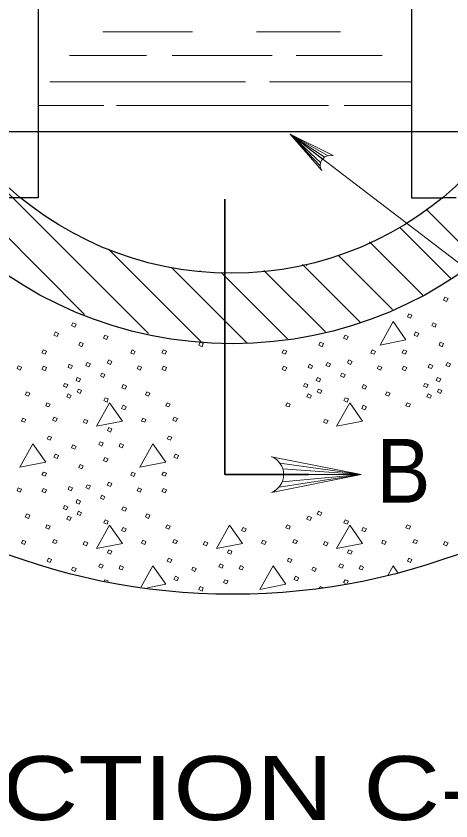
# Model space of a CAD drawing. Extents: x 1083.1 to 1117.1, y 719.4 to 741.4.
# Drawn here: x 1090.16 to 1091.793, y 732.034 to 735.057 of the extents above; entities that cross this region are included whole.
import ezdxf
from ezdxf.enums import TextEntityAlignment as Align

# ---------------------------------------------------------------- set-up
doc = ezdxf.new("R2010")
doc.units = 0
doc.header["$LTSCALE"] = 0.062
doc.linetypes.add('LONG_DASHED', pattern=[7.5, 6, -1.5])
doc.layers.add('1', color=7, linetype='Continuous', lineweight=13)

msp = doc.modelspace()

# ---------------------------------------------------------------- linework, layer by layer
at = {"layer": '1', "lineweight": 25}
for p, q in [((1090.24283, 736.2775), (1090.24283, 734.37467)), ((1091.64517, 736.2775), (1091.64517, 734.37467)), ((1090.24283, 734.62317), (1091.64517, 734.62317)), ((1091.64517, 734.37467), (1091.76217, 734.37467))]:
    msp.add_line(p, q, dxfattribs=at)
at = {"layer": '1'}
for p, q in [((1090.65658, 733.86433), (1089.491, 735.02975)), ((1090.48583, 734.99833), (1090.82275, 734.99833)), ((1091.06233, 734.99833), (1091.37825, 734.99833)), ((1090.36083, 734.90842), (1090.64908, 734.90842)), ((1090.74625, 734.90842), (1091.12133, 734.90842)), ((1091.21167, 734.90842), (1091.53458, 734.90842)), ((1090.41642, 733.93658), (1089.56367, 734.78925)), ((1090.28625, 734.81042), (1091.02067, 734.81042)), ((1091.11092, 734.81042), (1091.64517, 734.81042)), ((1090.24283, 734.72175), (1090.48883, 734.72175)), ((1090.53692, 734.72175), (1091.33317, 734.72175)), ((1091.39225, 734.72175), (1091.64517, 734.72175)), ((1091.31033, 734.5195), (1091.18858, 734.61392)), ((1091.30367, 734.50625), (1091.18858, 734.61392)), ((1091.30217, 734.49425), (1091.18858, 734.61392)), ((1091.31858, 734.52742), (1091.18858, 734.61392)), ((1091.32975, 734.53292), (1091.18858, 734.61392)), ((1091.89175, 734.13983), (1091.69958, 734.33208)), ((1091.79133, 734.07233), (1091.6, 734.26367)), ((1091.6875, 734.00842), (1091.487, 734.20883)), ((1090.854, 733.83467), (1090.50642, 734.18217)), ((1091.57283, 733.95525), (1091.36933, 734.15867)), ((1091.45242, 733.90775), (1091.236, 734.12417)), ((1091.02908, 733.8275), (1090.74475, 734.11175)), ((1091.17933, 733.84508), (1090.93025, 734.09417)), ((1091.32158, 733.87075), (1091.0905, 734.10183)), ((1091.15075, 733.3775), (1091.45517, 733.33492)), ((1091.16108, 733.35642), (1091.45517, 733.33492)), ((1091.14717, 733.28783), (1091.45517, 733.33492)), ((1091.15883, 733.30758), (1091.45517, 733.33492)), ((1091.16417, 733.33492), (1091.45517, 733.33492)), ((1090.67358, 732.99158), (1090.62983, 732.91325)), ((1091.57567, 732.99158), (1091.55717, 732.9585)), ((1091.59358, 732.96592), (1091.57567, 732.99158)), ((1090.49108, 732.93608), (1090.49317, 732.94017)), ((1091.29925, 732.908), (1091.30183, 732.91408))]:
    msp.add_line(p, q, dxfattribs=at)
at = {"layer": '1', "linetype": 'LONG_DASHED', "lineweight": 25}
for p, q in [((1087.08633, 734.62317), (1090.24283, 734.62317)), ((1091.64517, 734.62317), (1095.91342, 734.62317)), ((1090.24283, 734.37467), (1088.72042, 734.36742)), ((1093.22825, 734.37467), (1091.76217, 734.37467))]:
    msp.add_line(p, q, dxfattribs=at)
at = {"layer": '1', "lineweight": 35}
for p, q in [((1090.944, 734.37), (1090.944, 733.33492)), ((1090.944, 733.33492), (1091.25742, 733.33492))]:
    msp.add_line(p, q, dxfattribs=at)
at = {"layer": '1'}
for points in [[(1091.30742, 734.47658), (1091.18858, 734.61392), (1091.35108, 734.53292)], [(1091.18858, 734.61392), (1092.91808, 733.29283), (1093.25458, 733.29283)], [(1091.25342, 734.12575), (1091.25125, 734.12067), (1091.245, 734.12317)], [(1090.85208, 734.09967), (1090.85158, 734.0985), (1090.84875, 734.09983)], [(1091.11892, 733.26767), (1091.45517, 733.33492), (1091.11892, 733.40217)], [(1090.65342, 732.90942), (1090.72183, 732.92275), (1090.67358, 732.99158)], [(1090.49317, 732.94017), (1090.505, 732.93542), (1090.50433, 732.93392)], [(1091.30183, 732.91408), (1091.31375, 732.90933), (1091.31367, 732.90917)], [(1091.39742, 732.926), (1091.38967, 732.92908), (1091.39525, 732.94017)], [(1091.39525, 732.94017), (1091.40708, 732.93542), (1091.403, 732.92708)]]:
    msp.add_lwpolyline(points, dxfattribs=at)
for points in [[(1091.77033, 734.00117), (1091.78217, 733.99642), (1091.77667, 733.98533), (1091.76475, 733.99008)], [(1091.63417, 733.93867), (1091.64608, 733.93392), (1091.64133, 733.92283), (1091.62942, 733.92758)], [(1090.37292, 733.90542), (1090.38475, 733.89992), (1090.38, 733.88883), (1090.36808, 733.89433)], [(1091.57567, 733.90942), (1091.52658, 733.82158), (1091.62392, 733.84058)], [(1091.726, 733.90542), (1091.73783, 733.89992), (1091.73308, 733.88883), (1091.72125, 733.89433)], [(1090.30717, 733.87067), (1090.31908, 733.86508), (1090.3135, 733.854), (1090.30167, 733.85875)], [(1090.49317, 733.858), (1090.505, 733.85325), (1090.4995, 733.84217), (1090.48758, 733.84692)], [(1091.39525, 733.858), (1091.40708, 733.85325), (1091.40158, 733.84217), (1091.38967, 733.84692)], [(1091.66033, 733.87067), (1091.67217, 733.86508), (1091.66667, 733.854), (1091.65475, 733.85875)], [(1090.39975, 733.83183), (1090.41167, 733.82708), (1090.40692, 733.81525), (1090.395, 733.82075)], [(1090.85083, 733.83183), (1090.86267, 733.82708), (1090.85792, 733.81525), (1090.84608, 733.82075)], [(1091.30183, 733.83183), (1091.31375, 733.82708), (1091.309, 733.81525), (1091.29708, 733.82075)], [(1091.75292, 733.83183), (1091.76475, 733.82708), (1091.76, 733.81525), (1091.74817, 733.82075)], [(1090.26208, 733.80342), (1090.274, 733.79858), (1090.26842, 733.78758), (1090.25658, 733.79233)], [(1090.59525, 733.80342), (1090.60708, 733.79783), (1090.60233, 733.78675), (1090.5905, 733.7915)], [(1090.71317, 733.80342), (1090.725, 733.79858), (1090.7195, 733.78758), (1090.70758, 733.79233)], [(1091.16417, 733.80342), (1091.176, 733.79858), (1091.1705, 733.78758), (1091.15867, 733.79233)], [(1091.49733, 733.80342), (1091.50917, 733.79783), (1091.50442, 733.78675), (1091.49258, 733.7915)], [(1091.61517, 733.80342), (1091.62708, 733.79858), (1091.6215, 733.78758), (1091.60967, 733.79233)], [(1090.50742, 733.76542), (1090.51925, 733.75983), (1090.51375, 733.74875), (1090.50183, 733.75433)], [(1091.4095, 733.76542), (1091.42133, 733.75983), (1091.41583, 733.74875), (1091.40392, 733.75433)], [(1090.16792, 733.744), (1090.17983, 733.7385), (1090.17508, 733.72742), (1090.16317, 733.73292)], [(1090.26208, 733.74167), (1090.274, 733.73692), (1090.26842, 733.72508), (1090.25658, 733.73058)], [(1090.35942, 733.74958), (1090.37125, 733.744), (1090.36658, 733.73292), (1090.35467, 733.73767)], [(1090.42667, 733.75592), (1090.43858, 733.75117), (1090.433, 733.73925), (1090.42117, 733.74483)], [(1090.619, 733.744), (1090.63083, 733.7385), (1090.62608, 733.72742), (1090.61425, 733.73292)], [(1090.71317, 733.74167), (1090.725, 733.73692), (1090.7195, 733.72508), (1090.70758, 733.73058)], [(1091.16417, 733.74167), (1091.176, 733.73692), (1091.1705, 733.72508), (1091.15867, 733.73058)], [(1091.2615, 733.74958), (1091.27333, 733.744), (1091.26858, 733.73292), (1091.25675, 733.73767)], [(1091.32875, 733.75592), (1091.34067, 733.75117), (1091.33508, 733.73925), (1091.32325, 733.74483)], [(1091.521, 733.744), (1091.53292, 733.7385), (1091.52817, 733.72742), (1091.51633, 733.73292)], [(1091.61517, 733.74167), (1091.62708, 733.73692), (1091.6215, 733.72508), (1091.60967, 733.73058)], [(1091.7125, 733.74958), (1091.72442, 733.744), (1091.71967, 733.73292), (1091.70775, 733.73767)], [(1091.77983, 733.75592), (1091.79167, 733.75117), (1091.78608, 733.73925), (1091.77425, 733.74483)], [(1090.3895, 733.69975), (1090.40133, 733.69417), (1090.39658, 733.68308), (1090.38475, 733.68783)], [(1090.48125, 733.71633), (1090.49317, 733.71083), (1090.48842, 733.69975), (1090.4765, 733.70525)], [(1091.29158, 733.69975), (1091.30342, 733.69417), (1091.29867, 733.68308), (1091.28683, 733.68783)], [(1091.38333, 733.71633), (1091.39525, 733.71083), (1091.3905, 733.69975), (1091.37858, 733.70525)], [(1091.74258, 733.69975), (1091.7545, 733.69417), (1091.74975, 733.68308), (1091.73783, 733.68783)], [(1090.342, 733.67758), (1090.35392, 733.67283), (1090.34917, 733.66175), (1090.33725, 733.6665)], [(1090.562, 733.67283), (1090.57383, 733.66725), (1090.56908, 733.65625), (1090.55725, 733.66092)], [(1091.24408, 733.67758), (1091.25592, 733.67283), (1091.25125, 733.66175), (1091.23933, 733.6665)], [(1091.46408, 733.67283), (1091.47592, 733.66725), (1091.47117, 733.65625), (1091.45933, 733.66092)], [(1091.69517, 733.67758), (1091.707, 733.67283), (1091.70225, 733.66175), (1091.69042, 733.6665)], [(1090.19958, 733.64592), (1090.21142, 733.64117), (1090.20592, 733.62933), (1090.194, 733.63483)], [(1090.39342, 733.65625), (1090.40533, 733.65067), (1090.40058, 733.63958), (1090.38867, 733.64517)], [(1090.65058, 733.64592), (1090.6625, 733.64117), (1090.65692, 733.62933), (1090.64508, 733.63483)], [(1091.2955, 733.65625), (1091.30742, 733.65067), (1091.30267, 733.63958), (1091.29075, 733.64517)], [(1091.55267, 733.64592), (1091.56458, 733.64117), (1091.559, 733.62933), (1091.54717, 733.63483)], [(1091.74658, 733.65625), (1091.75842, 733.65067), (1091.75367, 733.63958), (1091.74183, 733.64517)], [(1090.35467, 733.638), (1090.36658, 733.6325), (1090.36183, 733.62142), (1090.34992, 733.62692)], [(1090.49392, 733.62375), (1090.50583, 733.619), (1090.50108, 733.60717), (1090.48917, 733.61267)], [(1091.25675, 733.638), (1091.26858, 733.6325), (1091.26383, 733.62142), (1091.252, 733.62692)], [(1091.396, 733.62375), (1091.40792, 733.619), (1091.40317, 733.60717), (1091.39125, 733.61267)], [(1091.70775, 733.638), (1091.71967, 733.6325), (1091.71492, 733.62142), (1091.703, 733.62692)], [(1090.27558, 733.60475), (1090.28742, 733.6), (1090.28267, 733.58892), (1090.27083, 733.59367)], [(1090.51058, 733.604), (1090.4615, 733.51617), (1090.55883, 733.53517)], [(1090.56117, 733.59525), (1090.57308, 733.58975), (1090.5675, 733.57867), (1090.55567, 733.58342)], [(1090.72658, 733.60475), (1090.73842, 733.6), (1090.73367, 733.58892), (1090.72183, 733.59367)], [(1091.17758, 733.60475), (1091.1895, 733.6), (1091.18475, 733.58892), (1091.17283, 733.59367)], [(1091.41267, 733.604), (1091.36358, 733.51617), (1091.46092, 733.53517)], [(1091.46325, 733.59525), (1091.47517, 733.58975), (1091.46958, 733.57867), (1091.45775, 733.58342)], [(1091.62867, 733.60475), (1091.6405, 733.6), (1091.63575, 733.58892), (1091.62392, 733.59367)], [(1090.30242, 733.55017), (1090.31433, 733.54542), (1090.30875, 733.53433), (1090.29692, 733.53908)], [(1090.7535, 733.55017), (1090.76533, 733.54542), (1090.75983, 733.53433), (1090.74792, 733.53908)], [(1090.18458, 733.547), (1090.19642, 733.54225), (1090.19167, 733.53117), (1090.17983, 733.53592)], [(1090.41717, 733.54225), (1090.42908, 733.5375), (1090.4235, 733.52642), (1090.41167, 733.53117)], [(1090.63558, 733.547), (1090.64742, 733.54225), (1090.64267, 733.53117), (1090.63083, 733.53592)], [(1091.31925, 733.54225), (1091.33117, 733.5375), (1091.32558, 733.52642), (1091.31375, 733.53117)], [(1090.50742, 733.51142), (1090.51925, 733.50667), (1090.5145, 733.49483), (1090.50267, 733.50033)], [(1090.28108, 733.47975), (1090.29292, 733.475), (1090.28817, 733.46392), (1090.27633, 733.46867)], [(1090.47492, 733.45842), (1090.48683, 733.45367), (1090.48208, 733.44183), (1090.47017, 733.44733)], [(1090.73208, 733.47975), (1090.744, 733.475), (1090.73925, 733.46392), (1090.72733, 733.46867)], [(1090.2225, 733.4505), (1090.1735, 733.36267), (1090.27083, 733.38167)], [(1090.37292, 733.4465), (1090.38475, 733.441), (1090.38, 733.42992), (1090.36808, 733.4355)], [(1090.55092, 733.45208), (1090.56275, 733.4465), (1090.558, 733.4355), (1090.54617, 733.44017)], [(1090.67358, 733.4505), (1090.6245, 733.36267), (1090.72183, 733.38167)], [(1090.30717, 733.41175), (1090.31908, 733.40617), (1090.3135, 733.39508), (1090.30167, 733.39983)], [(1090.49317, 733.39908), (1090.505, 733.39433), (1090.4995, 733.38325), (1090.48758, 733.388)], [(1090.75825, 733.41175), (1090.77008, 733.40617), (1090.76458, 733.39508), (1090.75267, 733.39983)], [(1090.39975, 733.37292), (1090.41167, 733.36825), (1090.40692, 733.35633), (1090.395, 733.36192)], [(1090.26208, 733.3445), (1090.274, 733.33975), (1090.26842, 733.32867), (1090.25658, 733.33342)], [(1090.59525, 733.3445), (1090.60708, 733.33892), (1090.60233, 733.32783), (1090.5905, 733.33258)], [(1090.71317, 733.3445), (1090.725, 733.33975), (1090.7195, 733.32867), (1090.70758, 733.33342)], [(1090.50742, 733.3065), (1090.51925, 733.30092), (1090.51375, 733.28992), (1090.50183, 733.29542)], [(1090.16792, 733.28517), (1090.17983, 733.27958), (1090.17508, 733.2685), (1090.16317, 733.27408)], [(1090.26208, 733.28275), (1090.274, 733.278), (1090.26842, 733.26617), (1090.25658, 733.27167)], [(1090.35942, 733.29067), (1090.37125, 733.28517), (1090.36658, 733.27408), (1090.35467, 733.27883)], [(1090.42667, 733.297), (1090.43858, 733.29225), (1090.433, 733.28042), (1090.42117, 733.28592)], [(1090.619, 733.28517), (1090.63083, 733.27958), (1090.62608, 733.2685), (1090.61425, 733.27408)], [(1090.71317, 733.28275), (1090.725, 733.278), (1090.7195, 733.26617), (1090.70758, 733.27167)], [(1090.48125, 733.25742), (1090.49317, 733.25192), (1090.48842, 733.24083), (1090.4765, 733.24633)], [(1090.342, 733.21867), (1090.35392, 733.21392), (1090.34917, 733.20283), (1090.33725, 733.20758)], [(1090.3895, 733.24083), (1090.40133, 733.23525), (1090.39658, 733.22417), (1090.38475, 733.22892)], [(1090.19958, 733.187), (1090.21142, 733.18225), (1090.20592, 733.17042), (1090.194, 733.17592)], [(1090.39342, 733.19733), (1090.40533, 733.19175), (1090.40058, 733.18067), (1090.38867, 733.18625)], [(1090.562, 733.21392), (1090.57383, 733.20842), (1090.56908, 733.19733), (1090.55725, 733.20208)], [(1090.65058, 733.187), (1090.6625, 733.18225), (1090.65692, 733.17042), (1090.64508, 733.17592)], [(1091.2955, 733.19733), (1091.30742, 733.19175), (1091.30267, 733.18067), (1091.29075, 733.18625)], [(1090.35467, 733.17908), (1090.36658, 733.17358), (1090.36183, 733.1625), (1090.34992, 733.168)], [(1090.49392, 733.16483), (1090.50583, 733.16008), (1090.50108, 733.14825), (1090.48917, 733.15375)], [(1091.25675, 733.17908), (1091.26858, 733.17358), (1091.26383, 733.1625), (1091.252, 733.168)], [(1091.396, 733.16483), (1091.40792, 733.16008), (1091.40317, 733.14825), (1091.39125, 733.15375)], [(1090.27558, 733.14592), (1090.28742, 733.14117), (1090.28267, 733.13008), (1090.27083, 733.13483)], [(1090.51058, 733.14508), (1090.4615, 733.05725), (1090.55883, 733.07625)], [(1090.56117, 733.13642), (1090.57308, 733.13083), (1090.5675, 733.11975), (1090.55567, 733.1245)], [(1090.72658, 733.14592), (1090.73842, 733.14117), (1090.73367, 733.13008), (1090.72183, 733.13483)], [(1090.96158, 733.14508), (1090.9125, 733.05725), (1091.00983, 733.07625)], [(1091.01225, 733.13642), (1091.02408, 733.13083), (1091.01858, 733.11975), (1091.00667, 733.1245)], [(1091.17758, 733.14592), (1091.1895, 733.14117), (1091.18475, 733.13008), (1091.17283, 733.13483)], [(1091.41267, 733.14508), (1091.36358, 733.05725), (1091.46092, 733.07625)], [(1091.46325, 733.13642), (1091.47517, 733.13083), (1091.46958, 733.11975), (1091.45775, 733.1245)], [(1091.62867, 733.14592), (1091.6405, 733.14117), (1091.63575, 733.13008), (1091.62392, 733.13483)], [(1090.18458, 733.08808), (1090.19642, 733.08333), (1090.19167, 733.07233), (1090.17983, 733.07708)], [(1090.30242, 733.09125), (1090.31433, 733.0865), (1090.30875, 733.0755), (1090.29692, 733.08017)], [(1090.41717, 733.08333), (1090.42908, 733.07858), (1090.4235, 733.06758), (1090.41167, 733.07233)], [(1090.63558, 733.08808), (1090.64742, 733.08333), (1090.64267, 733.07233), (1090.63083, 733.07708)], [(1090.7535, 733.09125), (1090.76533, 733.0865), (1090.75983, 733.0755), (1090.74792, 733.08017)], [(1090.86825, 733.08333), (1090.88008, 733.07858), (1090.87458, 733.06758), (1090.86267, 733.07233)], [(1091.08658, 733.08808), (1091.0985, 733.08333), (1091.09375, 733.07233), (1091.08183, 733.07708)], [(1091.2045, 733.09125), (1091.21642, 733.0865), (1091.21083, 733.0755), (1091.199, 733.08017)], [(1091.31925, 733.08333), (1091.33117, 733.07858), (1091.32558, 733.06758), (1091.31375, 733.07233)], [(1091.53767, 733.08808), (1091.5495, 733.08333), (1091.54475, 733.07233), (1091.53292, 733.07708)], [(1091.65558, 733.09125), (1091.66742, 733.0865), (1091.66192, 733.0755), (1091.65, 733.08017)], [(1091.77033, 733.08333), (1091.78217, 733.07858), (1091.77667, 733.06758), (1091.76475, 733.07233)], [(1090.50742, 733.0525), (1090.51925, 733.04775), (1090.5145, 733.03592), (1090.50267, 733.04142)], [(1090.95842, 733.0525), (1090.97033, 733.04775), (1090.96558, 733.03592), (1090.95367, 733.04142)], [(1091.4095, 733.0525), (1091.42133, 733.04775), (1091.41658, 733.03592), (1091.40475, 733.04142)], [(1090.28108, 733.02083), (1090.29292, 733.01608), (1090.28817, 733.00508), (1090.27633, 733.00975)], [(1090.73208, 733.02083), (1090.744, 733.01608), (1090.73925, 733.00508), (1090.72733, 733.00975)], [(1091.18317, 733.02083), (1091.195, 733.01608), (1091.19025, 733.00508), (1091.17842, 733.00975)], [(1091.63417, 733.02083), (1091.64608, 733.01608), (1091.64133, 733.00508), (1091.62942, 733.00975)], [(1090.37292, 732.98767), (1090.38475, 732.98208), (1090.38, 732.971), (1090.36808, 732.97658)], [(1090.47492, 732.9995), (1090.48683, 732.99475), (1090.48208, 732.98292), (1090.47017, 732.98842)], [(1090.55092, 732.99317), (1090.56275, 732.98767), (1090.558, 732.97658), (1090.54617, 732.98133)], [(1090.82392, 732.98767), (1090.83575, 732.98208), (1090.831, 732.971), (1090.81917, 732.97658)], [(1090.926, 732.9995), (1090.93783, 732.99475), (1090.93308, 732.98292), (1090.92125, 732.98842)], [(1091.00192, 732.99317), (1091.01383, 732.98767), (1091.00908, 732.97658), (1090.99717, 732.98133)], [(1091.12458, 732.99158), (1091.07558, 732.90375), (1091.17283, 732.92275)], [(1091.27492, 732.98767), (1091.28683, 732.98208), (1091.28208, 732.971), (1091.27017, 732.97658)], [(1091.377, 732.9995), (1091.38892, 732.99475), (1091.38417, 732.98292), (1091.37225, 732.98842)], [(1091.453, 732.99317), (1091.46483, 732.98767), (1091.46008, 732.97658), (1091.44825, 732.98133)], [(1090.75825, 732.95283), (1090.77008, 732.94725), (1090.76458, 732.93617), (1090.75267, 732.94092)], [(1091.20925, 732.95283), (1091.22117, 732.94725), (1091.21558, 732.93617), (1091.20375, 732.94092)], [(1090.85083, 732.91408), (1090.86267, 732.90933), (1090.85792, 732.89742), (1090.84608, 732.903)], [(1090.94417, 732.94017), (1090.95608, 732.93542), (1090.9505, 732.92433), (1090.93867, 732.92908)]]:
    msp.add_lwpolyline(points, close=True, dxfattribs=at)
msp.add_arc((1091.09174, 733.33497), 0.07258, 292.08605, 67.91218, dxfattribs=at)
at = {"layer": '1', "lineweight": 25}
for centre, major_axis in [((1090.97275, 735.33737), (2.45238, 0)), ((1090.9718, 735.34212), (1.5159, 0)), ((1090.96895, 735.34307), (1.25185, 0))]:
    msp.add_ellipse(centre, major_axis=major_axis, ratio=0.999895, dxfattribs=at)
at = {"layer": '1'}
msp.add_ellipse((1091.34065, 734.4959), major_axis=(0.02889, 0.02534), ratio=0.999895, start_param=0.5759874, end_param=2.9466005, dxfattribs=at)

# ---------------------------------------------------------------- texts
at = {"layer": '1', "width": 0.95}
msp.add_text('B', height=0.24, dxfattribs=at).set_placement((1091.6145, 733.22917), align=Align.CENTER)
at = {"layer": '1', "width": 1.25}
msp.add_text('SECTION C-C', height=0.24, dxfattribs=at).set_placement((1089.56842, 732.0375))

doc.saveas('drawing.dxf')
